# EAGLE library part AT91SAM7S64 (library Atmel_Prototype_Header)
Atmel AT91 ARM Thumb-based Microcontroller. LQFP64 package.
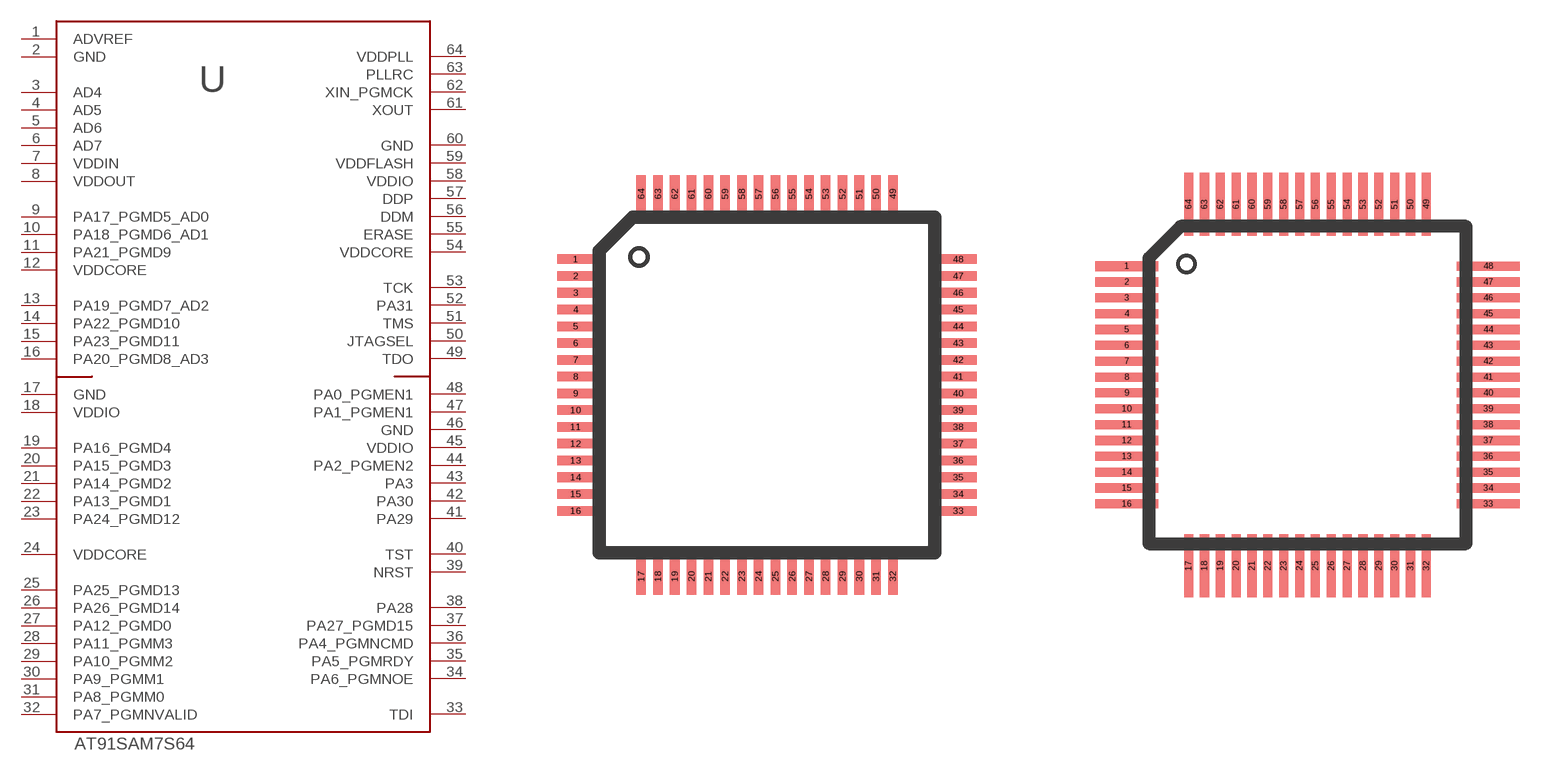
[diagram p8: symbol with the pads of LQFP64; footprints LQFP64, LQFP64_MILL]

Designator prefix U

## AT91SAM7S64_LQFP64  [LQFP64]
1  ADVREF  in
2  GND
3  AD4
4  AD5
5  AD6
6  AD7
7  VDDIN
8  VDDOUT
9  PA17_PGMD5_AD0
10  PA18_PGMD6_AD1
11  PA21_PGMD9
12  VDDCORE
13  PA19_PGMD7_AD2
14  PA22_PGMD10
15  PA23_PGMD11
16  PA20_PGMD8_AD3
17  GND
18  VDDIO
19  PA16_PGMD4
20  PA15_PGMD3  in
21  PA14_PGMD2  pwr
22  PA13_PGMD1  pwr
23  PA24_PGMD12
24  VDDCORE
25  PA25_PGMD13
26  PA26_PGMD14
27  PA12_PGMD0
28  PA11_PGMM3
29  PA10_PGMM2
30  PA9_PGMM1
31  PA8_PGMM0
32  PA7_PGMNVALID
33  TDI
34  PA6_PGMNOE
35  PA5_PGMRDY  out
36  PA4_PGMNCMD  out
37  PA27_PGMD15  out
38  PA28  out
39  NRST  out
40  TST  out
41  PA29  out
42  PA30  out
43  PA3
44  PA2_PGMEN2
45  VDDIO
46  GND
47  PA1_PGMEN1
48  PA0_PGMEN1
49  TDO
50  JTAGSEL
51  TMS
52  PA31  pwr
53  TCK  pwr
54  VDDCORE  in
55  ERASE  in
56  DDM  in
57  DDP  in
58  VDDIO  in
59  VDDFLASH  in
60  GND  in
61  XOUT  in
62  XIN_PGMCK
63  PLLRC
64  VDDPLL

## AT91SAM7S64_LQFP64_MILL  [LQFP64_MILL]
Pads as for LQFP64

## AT91SAM7S64_DUAL64_43  [HEADER_DUALSQR64_43]
Pads as for LQFP64

## AT91SAM7S64_DUAL64_35  [HEADER_DUALSQR64_35]
Pads as for LQFP64

## AT91SAM7S64_PLCC64_43  [HEADER_PLCC64_43]
Pads as for LQFP64

## AT91SAM7S64_PLCC64_35  [HEADER_PLCC64_35]
Pads as for LQFP64

## Footprint LQFP64 (pad centres in mm)
Plastic Low Profile Quad Flat Package. From ti_msp430.lbr
smd 1.1 x 0.285: 1 -5.7,3.75; 2 -5.7,3.25; 3 -5.7,2.75; 4 -5.7,2.25; 5 -5.7,1.75; 6 -5.7,1.25; 7 -5.7,0.75; 8 -5.7,0.25; 9 -5.7,-0.25; 10 -5.7,-0.75; 11 -5.7,-1.25; 12 -5.7,-1.75; 13 -5.7,-2.25; 14 -5.7,-2.75; 15 -5.7,-3.25; 16 -5.7,-3.75; 33 5.7,-3.75; 34 5.7,-3.25; 35 5.7,-2.75; 36 5.7,-2.25; 37 5.7,-1.75; 38 5.7,-1.25; 39 5.7,-0.75; 40 5.7,-0.25; 41 5.7,0.25; 42 5.7,0.75; 43 5.7,1.25; 44 5.7,1.75; 45 5.7,2.25; 46 5.7,2.75; 47 5.7,3.25; 48 5.7,3.75
smd 0.285 x 1.1: 17 -3.75,-5.7; 18 -3.25,-5.7; 19 -2.75,-5.7; 20 -2.25,-5.7; 21 -1.75,-5.7; 22 -1.25,-5.7; 23 -0.75,-5.7; 24 -0.25,-5.7; 25 0.25,-5.7; 26 0.75,-5.7; 27 1.25,-5.7; 28 1.75,-5.7; 29 2.25,-5.7; 30 2.75,-5.7; 31 3.25,-5.7; 32 3.75,-5.7; 49 3.75,5.7; 50 3.25,5.7; 51 2.75,5.7; 52 2.25,5.7; 53 1.75,5.7; 54 1.25,5.7; 55 0.75,5.7; 56 0.25,5.7; 57 -0.25,5.7; 58 -0.75,5.7; 59 -1.25,5.7; 60 -1.75,5.7; 61 -2.25,5.7; 62 -2.75,5.7; 63 -3.25,5.7; 64 -3.75,5.7

## Footprint LQFP64_MILL (pad centres in mm)
Plastic Low Profile Quad Flat Package. Mill spec. from ti_msp430.lbr
smd 2 x 0.287: 1 -5.7,3.75; 2 -5.7,3.25; 3 -5.7,2.75; 4 -5.7,2.25; 5 -5.7,1.75; 6 -5.7,1.25; 7 -5.7,0.75; 8 -5.7,0.25; 9 -5.7,-0.25; 10 -5.7,-0.75; 11 -5.7,-1.25; 12 -5.7,-1.75; 13 -5.7,-2.25; 14 -5.7,-2.75; 15 -5.7,-3.25; 16 -5.7,-3.75; 33 5.7,-3.75; 34 5.7,-3.25; 35 5.7,-2.75; 36 5.7,-2.25; 37 5.7,-1.75; 38 5.7,-1.25; 39 5.7,-0.75; 40 5.7,-0.25; 41 5.7,0.25; 42 5.7,0.75; 43 5.7,1.25; 44 5.7,1.75; 45 5.7,2.25; 46 5.7,2.75; 47 5.7,3.25; 48 5.7,3.75
smd 0.287 x 2: 17 -3.75,-5.7; 18 -3.25,-5.7; 19 -2.75,-5.7; 20 -2.25,-5.7; 21 -1.75,-5.7; 22 -1.25,-5.7; 23 -0.75,-5.7; 24 -0.25,-5.7; 25 0.25,-5.7; 26 0.75,-5.7; 27 1.25,-5.7; 28 1.75,-5.7; 29 2.25,-5.7; 30 2.75,-5.7; 31 3.25,-5.7; 32 3.75,-5.7; 49 3.75,5.7; 50 3.25,5.7; 51 2.75,5.7; 52 2.25,5.7; 53 1.75,5.7; 54 1.25,5.7; 55 0.75,5.7; 56 0.25,5.7; 57 -0.25,5.7; 58 -0.75,5.7; 59 -1.25,5.7; 60 -1.75,5.7; 61 -2.25,5.7; 62 -2.75,5.7; 63 -3.25,5.7; 64 -3.75,5.7

## Footprint HEADER_DUALSQR64_43 (pad centres in mm)
drill 1.1 square: 1 -13.97,8.89
drill 1.1 round: 2 -11.43,8.89; 3 -13.97,6.35; 4 -11.43,6.35; 5 -13.97,3.81; 6 -11.43,3.81; 7 -13.97,1.27; 8 -11.43,1.27; 9 -13.97,-1.27; 10 -11.43,-1.27; 11 -13.97,-3.81; 12 -11.43,-3.81; 13 -13.97,-6.35; 14 -11.43,-6.35; 15 -13.97,-8.89; 16 -11.43,-8.89; 17 -8.89,-13.97; 18 -8.89,-11.43; 19 -6.35,-13.97; 20 -6.35,-11.43; 21 -3.81,-13.97; 22 -3.81,-11.43; 23 -1.27,-13.97; 24 -1.27,-11.43; 25 1.27,-13.97; 26 1.27,-11.43; 27 3.81,-13.97; 28 3.81,-11.43; 29 6.35,-13.97; 30 6.35,-11.43; 31 8.89,-13.97; 32 8.89,-11.43; 33 13.97,-8.89; 34 11.43,-8.89; 35 13.97,-6.35; 36 11.43,-6.35; 37 13.97,-3.81; 38 11.43,-3.81; 39 13.97,-1.27; 40 11.43,-1.27; 41 13.97,1.27; 42 11.43,1.27; 43 13.97,3.81; 44 11.43,3.81; 45 13.97,6.35; 46 11.43,6.35; 47 13.97,8.89; 48 11.43,8.89; 49 8.89,13.97; 50 8.89,11.43; 51 6.35,13.97; 52 6.35,11.43; 53 3.81,13.97; 54 3.81,11.43; 55 1.27,13.97; 56 1.27,11.43; 57 -1.27,13.97; 58 -1.27,11.43; 59 -3.81,13.97; 60 -3.81,11.43; 61 -6.35,13.97; 62 -6.35,11.43; 63 -8.89,13.97; 64 -8.89,11.43

## Footprint HEADER_DUALSQR64_35 (pad centres in mm)
drill 0.9 square: 1 -13.97,8.89
drill 0.9 round: 2 -11.43,8.89; 3 -13.97,6.35; 4 -11.43,6.35; 5 -13.97,3.81; 6 -11.43,3.81; 7 -13.97,1.27; 8 -11.43,1.27; 9 -13.97,-1.27; 10 -11.43,-1.27; 11 -13.97,-3.81; 12 -11.43,-3.81; 13 -13.97,-6.35; 14 -11.43,-6.35; 15 -13.97,-8.89; 16 -11.43,-8.89; 17 -8.89,-13.97; 18 -8.89,-11.43; 19 -6.35,-13.97; 20 -6.35,-11.43; 21 -3.81,-13.97; 22 -3.81,-11.43; 23 -1.27,-13.97; 24 -1.27,-11.43; 25 1.27,-13.97; 26 1.27,-11.43; 27 3.81,-13.97; 28 3.81,-11.43; 29 6.35,-13.97; 30 6.35,-11.43; 31 8.89,-13.97; 32 8.89,-11.43; 33 13.97,-8.89; 34 11.43,-8.89; 35 13.97,-6.35; 36 11.43,-6.35; 37 13.97,-3.81; 38 11.43,-3.81; 39 13.97,-1.27; 40 11.43,-1.27; 41 13.97,1.27; 42 11.43,1.27; 43 13.97,3.81; 44 11.43,3.81; 45 13.97,6.35; 46 11.43,6.35; 47 13.97,8.89; 48 11.43,8.89; 49 8.89,13.97; 50 8.89,11.43; 51 6.35,13.97; 52 6.35,11.43; 53 3.81,13.97; 54 3.81,11.43; 55 1.27,13.97; 56 1.27,11.43; 57 -1.27,13.97; 58 -1.27,11.43; 59 -3.81,13.97; 60 -3.81,11.43; 61 -6.35,13.97; 62 -6.35,11.43; 63 -8.89,13.97; 64 -8.89,11.43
